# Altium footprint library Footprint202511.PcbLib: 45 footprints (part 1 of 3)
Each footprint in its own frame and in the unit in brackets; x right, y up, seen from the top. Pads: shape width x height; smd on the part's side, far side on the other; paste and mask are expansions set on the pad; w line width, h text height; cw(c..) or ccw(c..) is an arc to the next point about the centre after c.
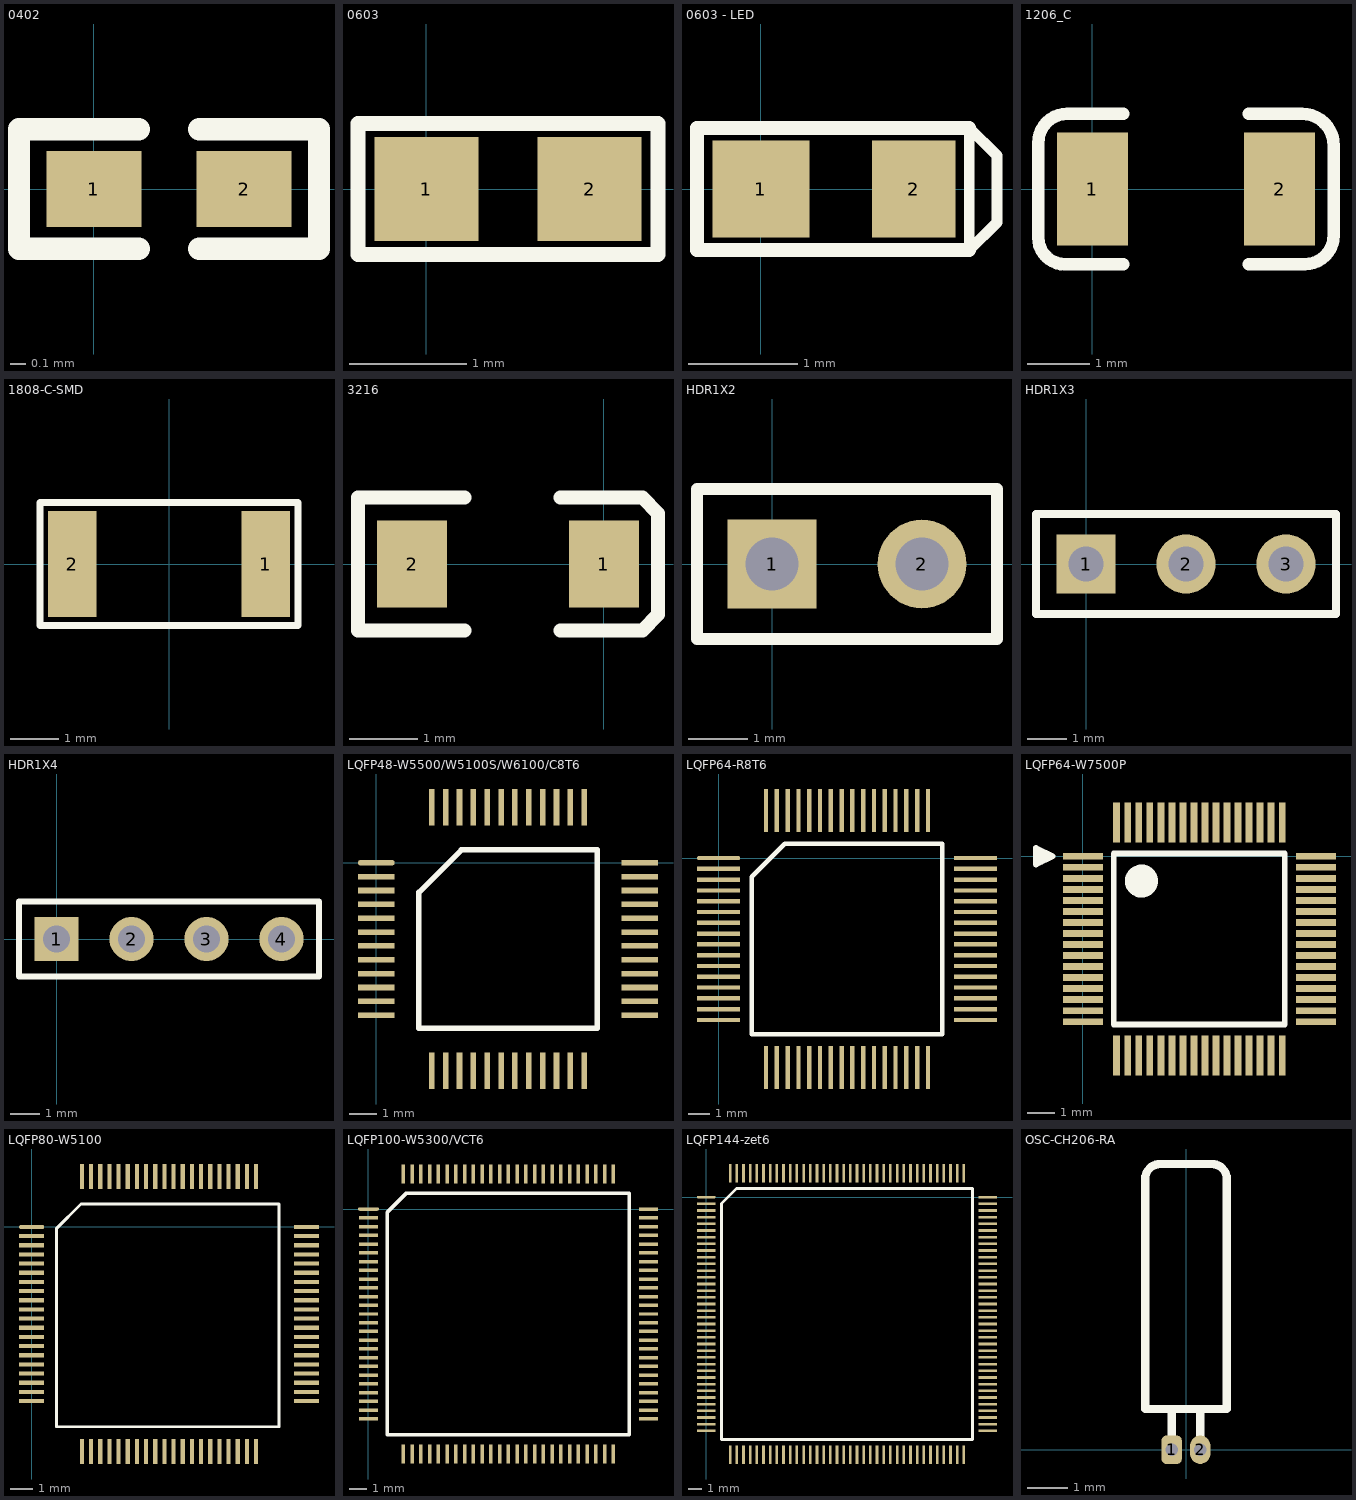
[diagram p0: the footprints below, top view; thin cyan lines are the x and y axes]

## 0402 [mil]
height 43.31
pads (2):
  rect 25x20 smd: 1(0,0) 2(39.37,0)
Top Overlay:
  lines w5.91: 11.81,-15.75 -19.68,-15.75 -19.68,15.75 11.81,15.75 ; 27.56,-15.75 59.06,-15.75 59.06,15.75 27.56,15.75

## 0603 [mil]
height 43.31
pads (2):
  rect 35x35 smd: 1(0,0) 2(55,0)
Top Overlay:
  lines w5: -23,-22 -23,22 78,22 78,-22 -23,-22

## 0603 - LED [mil]
height 43.31
pads (2):
  rect 35x35 smd: 1(0,0)
  rect 30x35 smd: 2(55,0)
Top Overlay:
  lines w3.94: 75,-22 75,22 85,12 85,-12 75,-22
  lines w5: 75,-22 -23,-22 -23,22 75,22

## 1206_C [mm]
pads (2):
  rect 1.13x1.8 smd: 1(0,0) 2(2.98,0)
Top Overlay:
  lines w0.2: 0.49,-1.2 -0.438,-1.2 cw(c-0.438,-0.773) -0.865,-0.773 -0.865,0.733 cw(c-0.398,0.733) -0.398,1.2 0.49,1.2 ; 2.49,-1.2 3.38,-1.2 ccw(c3.38,-0.735) 3.845,-0.735 3.845,0.692 ccw(c3.337,0.692) 3.337,1.2 2.49,1.2

## 1808-C-SMD [mm] "1808-C-SMD"
pads (2):
  rect 1x2.2 smd: 1(2,0) 2(-2,0)
Top Overlay:
  lines w0.152: -2.667,-1.27 -2.667,1.27 2.667,1.27 2.667,-1.27 -2.667,-1.27

## 3216 [mil]
height 43.31
pads (2):
  rect 40x50 smd: 1(0,0) 2(-110,0)
Top Overlay:
  lines w8: -80,-38 -141,-38 -141,38 -80,38 ; -25,-38 22,-38 31,-29 31,29 22,38 -25,38

## HDR1X2 [mm]
height 0.55
pads (2):
  rect 1.5x1.5 hole 0.9: 1(0,0)
  round 1.5 hole 0.9: 2(2.54,0)
Top Overlay:
  lines w0.2: -1.27,-1.27 3.81,-1.27 3.81,1.27 -1.27,1.27 -1.27,-1.27

## HDR1X3 [mm] "Connector; Header; 3 Position"
height 1.1
pads (3):
  rect 1.5x1.5 hole 0.9: 1(0,0)
  round 1.5 hole 0.9: 2(2.54,0) 3(5.08,0)
Top Overlay:
  lines w0.2: -1.27,-1.27 -1.27,1.27 6.35,1.27 6.35,-1.27 -1.27,-1.27

## HDR1X4 [mm] "Connector; Header; 4 Position"
pads (4):
  rect 1.5x1.5 hole 0.9: 1(0,0)
  round 1.5 hole 0.9: 2(2.54,0) 3(5.08,0) 4(7.62,0)
Top Overlay:
  lines w0.2: -1.27,-1.27 8.89,-1.27 8.89,1.27 -1.27,1.27 -1.27,-1.27

## LQFP48-W5500/W5100S/W6100/C8T6 [mm]
pads (48):
  oval 1.321x0.2 smd: 1(0,0)
  rect 1.321x0.2 smd: 2(0,-0.5) 3(0,-1) 4(0,-1.5) 5(0,-2) 6(0,-2.5) 7(0,-3) 8(0,-3.5) 9(0,-4) 10(0,-4.5) 11(0,-5) 12(0,-5.5) 25(9.5,-5.5) 26(9.5,-5) 27(9.5,-4.5) 28(9.5,-4) 29(9.5,-3.5) 30(9.5,-3) 31(9.5,-2.5) 32(9.5,-2) 33(9.5,-1.5) 34(9.5,-1) 35(9.5,-0.5) 36(9.5,0)
  rect 0.2x1.321 smd: 13(2,-7.5) 14(2.5,-7.5) 15(3,-7.5) 16(3.5,-7.5) 17(4,-7.5) 18(4.5,-7.5) 19(5,-7.5) 20(5.5,-7.5) 21(6,-7.5) 22(6.5,-7.5) 23(7,-7.5) 24(7.5,-7.5) 37(7.5,2) 38(7,2) 39(6.5,2) 40(6,2) 41(5.5,2) 42(5,2) 43(4.5,2) 44(4,2) 45(3.5,2) 46(3,2) 47(2.5,2) 48(2,2)
Top Overlay:
  lines w0.2: 1.535,-5.965 1.535,-1.07 3.07,0.465 7.965,0.465 7.965,-5.965 1.535,-5.965

## LQFP64-R8T6 [mm]
pads (64):
  oval 2x0.2 smd: 1(0,0)
  rect 2x0.2 smd: 2(0,-0.5) 3(0,-1) 4(0,-1.5) 5(0,-2) 6(0,-2.5) 7(0,-3) 8(0,-3.5) 9(0,-4) 10(0,-4.5) 11(0,-5) 12(0,-5.5) 13(0,-6) 14(0,-6.5) 15(0,-7) 16(0,-7.5) 33(11.9,-7.5) 34(11.9,-7) 35(11.9,-6.5) 36(11.9,-6) 37(11.9,-5.5) 38(11.9,-5) 39(11.9,-4.5) 40(11.9,-4) 41(11.9,-3.5) 42(11.9,-3) 43(11.9,-2.5) 44(11.9,-2) 45(11.9,-1.5) 46(11.9,-1) 47(11.9,-0.5) 48(11.9,0)
  rect 0.2x2 smd: 17(2.2,-9.7) 18(2.7,-9.7) 19(3.2,-9.7) 20(3.7,-9.7) 21(4.2,-9.7) 22(4.7,-9.7) 23(5.2,-9.7) 24(5.7,-9.7) 25(6.2,-9.7) 26(6.7,-9.7) 27(7.2,-9.7) 28(7.7,-9.7) 29(8.2,-9.7) 30(8.7,-9.7) 31(9.2,-9.7) 32(9.7,-9.7) 49(9.7,2.2) 50(9.2,2.2) 51(8.7,2.2) 52(8.2,2.2) 53(7.7,2.2) 54(7.2,2.2) 55(6.7,2.2) 56(6.2,2.2) 57(5.7,2.2) 58(5.2,2.2) 59(4.7,2.2) 60(4.2,2.2) 61(3.7,2.2) 62(3.2,2.2) 63(2.7,2.2) 64(2.2,2.2)
Top Overlay:
  lines w0.2: 1.535,-8.165 10.365,-8.165 10.365,0.665 3.07,0.665 1.535,-0.87 1.535,-8.165

## LQFP64-W7500P [mm]
pads (64):
  rect 1.45x0.25 smd: 1(0,0) 2(0,-0.4) 3(0,-0.8) 4(0,-1.2) 5(0,-1.6) 6(0,-2) 7(0,-2.4) 8(0,-2.8) 9(0,-3.2) 10(0,-3.6) 11(0,-4) 12(0,-4.4) 13(0,-4.8) 14(0,-5.2) 15(0,-5.6) 16(0,-6) 33(8.45,-6) 34(8.45,-5.6) 35(8.45,-5.2) 36(8.45,-4.8) 37(8.45,-4.4) 38(8.45,-4) 39(8.45,-3.6) 40(8.45,-3.2) 41(8.45,-2.8) 42(8.45,-2.4) 43(8.45,-2) 44(8.45,-1.6) 45(8.45,-1.2) 46(8.45,-0.8) 47(8.45,-0.4) 48(8.45,0)
  rect 0.25x1.45 smd: 17(1.225,-7.225) 18(1.625,-7.225) 19(2.025,-7.225) 20(2.425,-7.225) 21(2.825,-7.225) 22(3.225,-7.225) 23(3.625,-7.225) 24(4.025,-7.225) 25(4.425,-7.225) 26(4.825,-7.225) 27(5.225,-7.225) 28(5.625,-7.225) 29(6.025,-7.225) 30(6.425,-7.225) 31(6.825,-7.225) 32(7.225,-7.225) 49(7.225,1.225) 50(6.825,1.225) 51(6.425,1.225) 52(6.025,1.225) 53(5.625,1.225) 54(5.225,1.225) 55(4.825,1.225) 56(4.425,1.225) 57(4.025,1.225) 58(3.625,1.225) 59(3.225,1.225) 60(2.825,1.225) 61(2.425,1.225) 62(2.025,1.225) 63(1.625,1.225) 64(1.225,1.225)
Top Overlay:
  circle w0.6: c2.125,-0.9 r0.3
  lines w0.202: -1.699,0.138 -1.412,0.138 ; -1.498,-0.199 -1.498,-0.191 -1.688,0 -1.099,0 ; -1.099,0 -1.699,0.3 -1.699,-0.3 -1.099,0 ; 1.125,-6.1 7.325,-6.1 7.325,0.1 1.125,0.1 1.125,-6.1

## LQFP80-W5100 [mm]
pads (80):
  oval 1.1x0.18 smd: 1(0,0)
  rect 1.1x0.18 smd: 2(0,-0.4) 3(0,-0.8) 4(0,-1.2) 5(0,-1.6) 6(0,-2) 7(0,-2.4) 8(0,-2.8) 9(0,-3.2) 10(0,-3.6) 11(0,-4) 12(0,-4.4) 13(0,-4.8) 14(0,-5.2) 15(0,-5.6) 16(0,-6) 17(0,-6.4) 18(0,-6.8) 19(0,-7.2) 20(0,-7.6) 41(12,-7.6) 42(12,-7.2) 43(12,-6.8) 44(12,-6.4) 45(12,-6) 46(12,-5.6) 47(12,-5.2) 48(12,-4.8) 49(12,-4.4) 50(12,-4) 51(12,-3.6) 52(12,-3.2) 53(12,-2.8) 54(12,-2.4) 55(12,-2) 56(12,-1.6) 57(12,-1.2) 58(12,-0.8) 59(12,-0.4) 60(12,0)
  rect 0.18x1.1 smd: 21(2.2,-9.8) 22(2.6,-9.8) 23(3,-9.8) 24(3.4,-9.8) 25(3.8,-9.8) 26(4.2,-9.8) 27(4.6,-9.8) 28(5,-9.8) 29(5.4,-9.8) 30(5.8,-9.8) 31(6.2,-9.8) 32(6.6,-9.8) 33(7,-9.8) 34(7.4,-9.8) 35(7.8,-9.8) 36(8.2,-9.8) 37(8.6,-9.8) 38(9,-9.8) 39(9.4,-9.8) 40(9.8,-9.8) 61(9.8,2.2) 62(9.4,2.2) 63(9,2.2) 64(8.6,2.2) 65(8.2,2.2) 66(7.8,2.2) 67(7.4,2.2) 68(7,2.2) 69(6.6,2.2) 70(6.2,2.2) 71(5.8,2.2) 72(5.4,2.2) 73(5,2.2) 74(4.6,2.2) 75(4.2,2.2) 76(3.8,2.2) 77(3.4,2.2) 78(3,2.2) 79(2.6,2.2) 80(2.2,2.2)
Top Overlay:
  lines w0.127: 1.079,-8.725 10.808,-8.725 10.808,1.003 2.159,1.003 1.079,-0.076 1.079,-8.725

## LQFP100-W5300/VCT6 [mm]
pads (100):
  oval 1.2x0.2 smd: 1(0,0)
  rect 1.1x0.2 smd: 2(0,-0.5) 3(0,-1) 4(0,-1.5) 5(0,-2) 6(0,-2.5) 7(0,-3) 8(0,-3.5) 9(0,-4) 10(0,-4.5) 11(0,-5) 12(0,-5.5) 13(0,-6) 14(0,-6.5) 15(0,-7) 16(0,-7.5) 17(0,-8) 18(0,-8.5) 19(0,-9) 20(0,-9.5) 21(0,-10) 22(0,-10.5) 23(0,-11) 24(0,-11.5) 25(0,-12) 51(16,-12) 52(16,-11.5) 53(16,-11) 54(16,-10.5) 55(16,-10) 56(16,-9.5) 57(16,-9) 58(16,-8.5) 59(16,-8) 60(16,-7.5) 61(16,-7) 62(16,-6.5) 63(16,-6) 64(16,-5.5) 65(16,-5) 66(16,-4.5) 67(16,-4) 68(16,-3.5) 69(16,-3) 70(16,-2.5) 71(16,-2) 72(16,-1.5) 73(16,-1) 74(16,-0.5) 75(16,0)
  rect 0.2x1.1 smd: 26(2,-14) 27(2.5,-14) 28(3,-14) 29(3.5,-14) 30(4,-14) 31(4.5,-14) 32(5,-14) 33(5.5,-14) 34(6,-14) 35(6.5,-14) 36(7,-14) 37(7.5,-14) 38(8,-14) 39(8.5,-14) 40(9,-14) 41(9.5,-14) 42(10,-14) 43(10.5,-14) 44(11,-14) 45(11.5,-14) 46(12,-14) 47(12.5,-14) 48(13,-14) 49(13.5,-14) 50(14,-14) 76(14,2) 77(13.5,2) 78(13,2) 79(12.5,2) 80(12,2) 81(11.5,2) 82(11,2) 83(10.5,2) 84(10,2) 85(9.5,2) 86(9,2) 87(8.5,2) 88(8,2) 89(7.5,2) 90(7,2) 91(6.5,2) 92(6,2) 93(5.5,2) 94(5,2) 95(4.5,2) 96(4,2) 97(3.5,2) 98(3,2) 99(2.5,2) 100(2,2)
Top Overlay:
  lines w0.2: 1.085,-12.915 14.915,-12.915 14.915,0.915 2.17,0.915 1.085,-0.17 1.085,-12.915

## LQFP144-zet6 [mm]
pads (144):
  oval 1.4x0.2 smd: 1(0,0)
  rect 1.4x0.2 smd: 2(0,-0.5) 3(0,-1) 4(0,-1.5) 5(0,-2) 6(0,-2.5) 7(0,-3) 8(0,-3.5) 9(0,-4) 10(0,-4.5) 11(0,-5) 12(0,-5.5) 13(0,-6) 14(0,-6.5) 15(0,-7) 16(0,-7.5) 17(0,-8) 18(0,-8.5) 19(0,-9) 20(0,-9.5) 21(0,-10) 22(0,-10.5) 23(0,-11) 24(0,-11.5) 25(0,-12) 26(0,-12.5) 27(0,-13) 28(0,-13.5) 29(0,-14) 30(0,-14.5) 31(0,-15) 32(0,-15.5) 33(0,-16) 34(0,-16.5) 35(0,-17) 36(0,-17.5) 73(21.06,-17.5) 74(21.06,-17) 75(21.06,-16.5) 76(21.06,-16) 77(21.06,-15.5) 78(21.06,-15) 79(21.06,-14.5) 80(21.06,-14) 81(21.06,-13.5) 82(21.06,-13) 83(21.06,-12.5) 84(21.06,-12) 85(21.06,-11.5) 86(21.06,-11) 87(21.06,-10.5) 88(21.06,-10) 89(21.06,-9.5) 90(21.06,-9) 91(21.06,-8.5) 92(21.06,-8) 93(21.06,-7.5) 94(21.06,-7) 95(21.06,-6.5) 96(21.06,-6) 97(21.06,-5.5) 98(21.06,-5) 99(21.06,-4.5) 100(21.06,-4) 101(21.06,-3.5) 102(21.06,-3) 103(21.06,-2.5) 104(21.06,-2) 105(21.06,-1.5) 106(21.06,-1) 107(21.06,-0.5) 108(21.06,0)
  rect 0.2x1.4 smd: 37(1.78,-19.28) 38(2.28,-19.28) 39(2.78,-19.28) 40(3.28,-19.28) 41(3.78,-19.28) 42(4.28,-19.28) 43(4.78,-19.28) 44(5.28,-19.28) 45(5.78,-19.28) 46(6.28,-19.28) 47(6.78,-19.28) 48(7.28,-19.28) 49(7.78,-19.28) 50(8.28,-19.28) 51(8.78,-19.28) 52(9.28,-19.28) 53(9.78,-19.28) 54(10.28,-19.28) 55(10.78,-19.28) 56(11.28,-19.28) 57(11.78,-19.28) 58(12.28,-19.28) 59(12.78,-19.28) 60(13.28,-19.28) 61(13.78,-19.28) 62(14.28,-19.28) 63(14.78,-19.28) 64(15.28,-19.28) 65(15.78,-19.28) 66(16.28,-19.28) 67(16.78,-19.28) 68(17.28,-19.28) 69(17.78,-19.28) 70(18.28,-19.28) 71(18.78,-19.28) 72(19.28,-19.28) 109(19.28,1.78) 110(18.78,1.78) 111(18.28,1.78) 112(17.78,1.78) 113(17.28,1.78) 114(16.78,1.78) 115(16.28,1.78) 116(15.78,1.78) 117(15.28,1.78) 118(14.78,1.78) 119(14.28,1.78) 120(13.78,1.78) 121(13.28,1.78) 122(12.78,1.78) 123(12.28,1.78) 124(11.78,1.78) 125(11.28,1.78) 126(10.78,1.78) 127(10.28,1.78) 128(9.78,1.78) 129(9.28,1.78) 130(8.78,1.78) 131(8.28,1.78) 132(7.78,1.78) 133(7.28,1.78) 134(6.78,1.78) 135(6.28,1.78) 136(5.78,1.78) 137(5.28,1.78) 138(4.78,1.78) 139(4.28,1.78) 140(3.78,1.78) 141(3.28,1.78) 142(2.78,1.78) 143(2.28,1.78) 144(1.78,1.78)
Top Overlay:
  lines w0.2: 1.135,-18.145 19.925,-18.145 19.925,0.645 2.27,0.645 1.135,-0.49 1.135,-18.145

## OSC-CH206-RA [mm]
height 3.9
pads (2):
  rrect50% 0.5x0.7 hole 0.3: 1(-0.35,0)
  oval 0.5x0.7 hole 0.3: 2(0.35,0)
Top Overlay:
  lines w0.202: -1,6.635 -1,6.604 -1,1 1,1 1,6.635 ; -0.604,7 0.635,7 ; -0.35,0 -0.35,1 ; 0.35,0 0.35,1
  lines w0.203: -1,6.635 cw(c-0.635,6.635) -0.635,7 ; 0.635,7 cw(c0.635,6.635) 1,6.635
3D body: height 2.1, standoff -0.77, extent -1,-0.127 1,6.998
